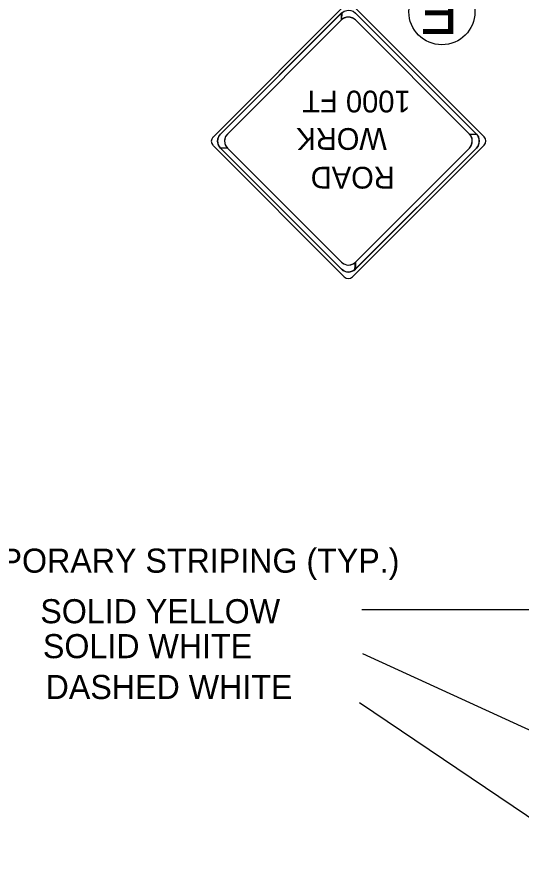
# Model space of a CAD drawing. Extents: x 1531.4 to 1538.6, y 1529.6 to 1539.6.
# Drawn here: x 1533.692 to 1534.948, y 1533.633 to 1535.739 of the extents above; entities that cross this region are included whole.
import ezdxf

# ---------------------------------------------------------------- set-up
doc = ezdxf.new("R2010")
doc.units = 0
for name, color, linetype in [('DETL-DIMS', 7, 'Continuous'), ('DETL-LINE', 7, 'Continuous'), ('DETL-NOTE', 7, 'Continuous')]:
    doc.layers.add(name, color=color, linetype=linetype)

msp = doc.modelspace()

# ---------------------------------------------------------------- linework, layer by layer
at = {"layer": 'DETL-DIMS'}
for p, q in [((1535.2116, 1534.262), (1534.5515, 1534.262)), ((1534.5535, 1534.1532), (1535.1434, 1533.8826)), ((1534.5458, 1534.0314), (1535.2841, 1533.5316))]:
    msp.add_line(p, q, dxfattribs=at)
at = {"layer": 'DETL-LINE'}
for p, q in [((1534.5086, 1535.7671), (1534.1806, 1535.4391)), ((1534.8561, 1535.4398), (1534.5289, 1535.7671)), ((1534.199, 1535.4468), (1534.5006, 1535.7484)), ((1534.5354, 1535.7484), (1534.837, 1535.4468)), ((1534.5006, 1535.731), (1534.2164, 1535.4468)), ((1534.8196, 1535.4468), (1534.5353, 1535.731)), ((1534.1806, 1535.4188), (1534.5078, 1535.0916)), ((1534.5006, 1535.1104), (1534.199, 1535.412)), ((1534.2164, 1535.412), (1534.5006, 1535.1278)), ((1534.5281, 1535.0916), (1534.8561, 1535.4196)), ((1534.837, 1535.412), (1534.5354, 1535.1104)), ((1534.5354, 1535.1278), (1534.8196, 1535.412))]:
    msp.add_line(p, q, dxfattribs=at)
for points in [[(1534.199, 1535.4468), (1534.4919, 1535.7396), (1534.5016, 1535.7494), (1534.5006, 1535.731), (1534.2164, 1535.4468), (1534.2118, 1535.4406), (1534.2092, 1535.4316), (1534.21, 1535.4232), (1534.2122, 1535.4175), (1534.2164, 1535.412), (1534.199, 1535.412), (1534.194, 1535.419), (1534.1918, 1535.4285), (1534.1925, 1535.4354), (1534.1948, 1535.4411)], [(1534.5353, 1535.7483), (1534.8282, 1535.4554), (1534.838, 1535.4457), (1534.8196, 1535.4468), (1534.5354, 1535.731), (1534.5292, 1535.7355), (1534.5201, 1535.7381), (1534.5118, 1535.7374), (1534.506, 1535.7351), (1534.5006, 1535.731), (1534.5006, 1535.7483), (1534.5076, 1535.7533), (1534.517, 1535.7556), (1534.524, 1535.7548), (1534.5297, 1535.7526)], [(1534.8369, 1535.412), (1534.544, 1535.1191), (1534.5342, 1535.1094), (1534.5353, 1535.1278), (1534.8196, 1535.412), (1534.824, 1535.4181), (1534.8266, 1535.4272), (1534.826, 1535.4356), (1534.8237, 1535.4413), (1534.8196, 1535.4468), (1534.8369, 1535.4468), (1534.8418, 1535.4397), (1534.8441, 1535.4303), (1534.8434, 1535.4234), (1534.8412, 1535.4176)], [(1534.5006, 1535.1104), (1534.2077, 1535.4033), (1534.1979, 1535.4131), (1534.2164, 1535.412), (1534.5005, 1535.1278), (1534.5067, 1535.1233), (1534.5158, 1535.1207), (1534.5241, 1535.1214), (1534.5298, 1535.1236), (1534.5353, 1535.1278), (1534.5353, 1535.1104), (1534.5283, 1535.1055), (1534.5188, 1535.1032), (1534.5119, 1535.104), (1534.5062, 1535.1062)]]:
    msp.add_lwpolyline(points, close=True, dxfattribs=at)
msp.add_circle((1534.751, 1535.7517), 0.0824, dxfattribs=at)
for centre, radius, start, end in [((1534.5179, 1535.7136), 0.0246, 45, 135), ((1534.1907, 1535.429), 0.0144, 135, 225), ((1534.2164, 1535.4294), 0.0246, 135, 225), ((1534.2338, 1535.4294), 0.0246, 135, 225), ((1534.8022, 1535.4294), 0.0246, 315, 45), ((1534.8196, 1535.4294), 0.0246, 315, 45), ((1534.846, 1535.4297), 0.0144, 315, 45), ((1534.518, 1535.1452), 0.0246, 225, 315), ((1534.518, 1535.1278), 0.0246, 225, 315), ((1534.518, 1535.1017), 0.0144, 225, 315)]:
    msp.add_arc(centre, radius, start, end, dxfattribs=at)

# ---------------------------------------------------------------- texts
for s, height, p in [('E', 0.1082, (1534.7916, 1535.8044)), ('1000 FT', 0.05416, (1534.673, 1535.555)), ('WORK', 0.05416, (1534.6136, 1535.4617)), ('ROAD ', 0.05416, (1534.6334, 1535.3653))]:
    msp.add_text(s, height=height, rotation=180, dxfattribs=at).set_placement(p)
at = {"layer": 'DETL-NOTE'}
for s, p in [('TEMPORARY STRIPING (TYP.)', (1533.4817, 1534.3543)), ('SOLID YELLOW', (1533.7502, 1534.2284)), ('SOLID WHITE', (1533.7567, 1534.1414)), ('DASHED WHITE', (1533.7634, 1534.0397))]:
    msp.add_text(s, height=0.06, dxfattribs=at).set_placement(p)

doc.saveas('drawing.dxf')
